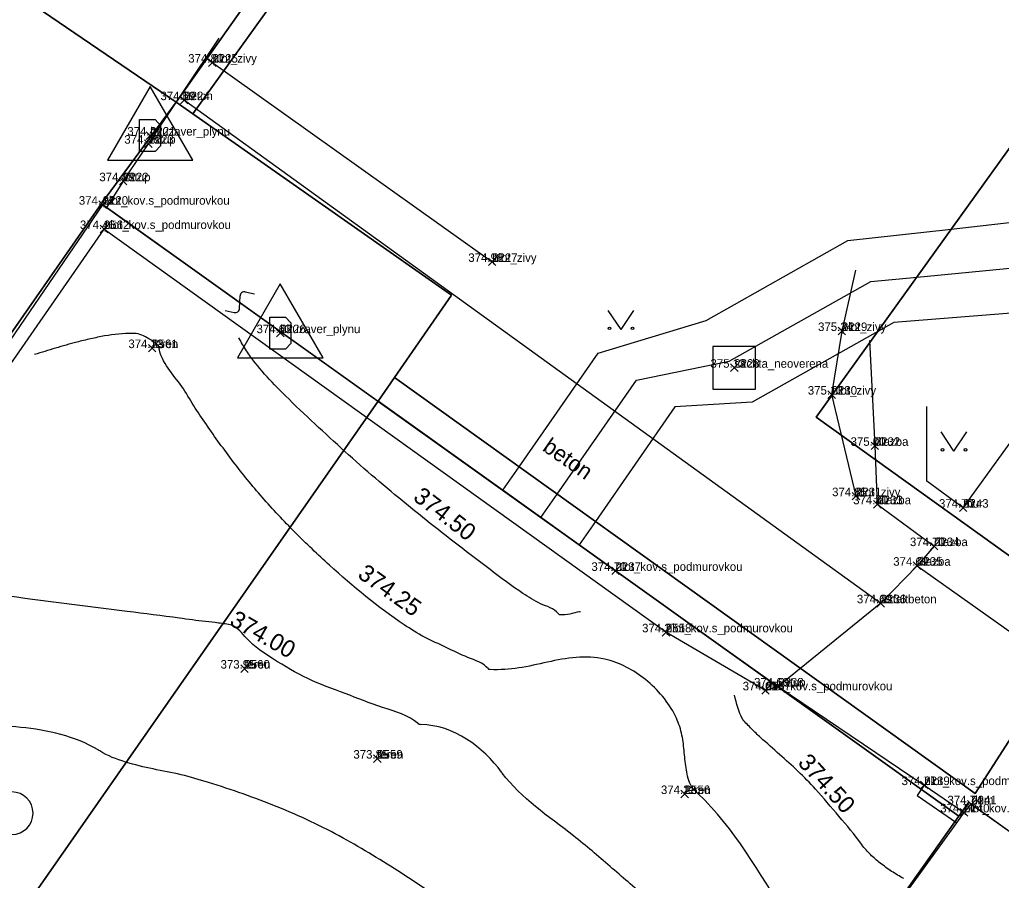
# Model space of a CAD drawing. Extents: x -400488 to -400124, y -1251493 to -1251223.
# Drawn here: x -400361.06 to -400338.08, y -1251307.23 to -1251287.06 of the extents above; entities that cross this region are included whole.
import ezdxf

# ---------------------------------------------------------------- set-up
doc = ezdxf.new("R2010")
doc.units = 0
for name, color, linetype in [('Level 20', 7, 'Continuous'), ('Level 21', 7, 'Continuous'), ('Level 22', 7, 'Continuous'), ('Level 23', 7, 'Continuous'), ('Level 31', 7, 'Continuous'), ('Level 32', 7, 'Continuous'), ('Level 34', 7, 'Continuous'), ('Level 35', 7, 'Continuous'), ('Level 36', 7, 'Continuous'), ('Level 49', 7, 'Continuous'), ('Level 50', 7, 'Continuous'), ('Level 60', 7, 'Continuous'), ('Level 63', 7, 'Continuous')]:
    doc.layers.add(name, color=color, linetype=linetype)

msp = doc.modelspace()

# ---------------------------------------------------------------- linework, layer by layer
at = {"layer": 'Level 20'}
for p, q in [((-400356.638, -1251288.158), (-400356.462, -1251287.982)), ((-400356.462, -1251288.158), (-400356.638, -1251287.982)), ((-400357.298, -1251289.038), (-400357.122, -1251288.862)), ((-400357.122, -1251289.038), (-400357.298, -1251288.862)), ((-400358.098, -1251289.868), (-400357.922, -1251289.692)), ((-400357.922, -1251289.868), (-400358.098, -1251289.692)), ((-400358.138, -1251290.058), (-400357.962, -1251289.882)), ((-400357.962, -1251290.058), (-400358.138, -1251289.882)), ((-400358.728, -1251290.938), (-400358.552, -1251290.762)), ((-400358.552, -1251290.938), (-400358.728, -1251290.762)), ((-400359.208, -1251291.488), (-400359.032, -1251291.312)), ((-400359.032, -1251291.488), (-400359.208, -1251291.312)), ((-400359.178, -1251292.058), (-400359.002, -1251291.882)), ((-400359.002, -1251292.058), (-400359.178, -1251291.882)), ((-400350.088, -1251292.828), (-400349.912, -1251292.652)), ((-400349.912, -1251292.828), (-400350.088, -1251292.652)), ((-400355.048, -1251294.498), (-400354.872, -1251294.322)), ((-400354.872, -1251294.498), (-400355.048, -1251294.322)), ((-400341.898, -1251294.448), (-400341.722, -1251294.272)), ((-400341.722, -1251294.448), (-400341.898, -1251294.272)), ((-400358.048, -1251294.848), (-400357.872, -1251294.672)), ((-400357.872, -1251294.848), (-400358.048, -1251294.672)), ((-400344.418, -1251295.308), (-400344.242, -1251295.132)), ((-400344.242, -1251295.308), (-400344.418, -1251295.132)), ((-400342.138, -1251295.938), (-400341.962, -1251295.762)), ((-400341.962, -1251295.938), (-400342.138, -1251295.762)), ((-400341.128, -1251297.138), (-400340.952, -1251296.962)), ((-400340.952, -1251297.138), (-400341.128, -1251296.962)), ((-400341.568, -1251298.318), (-400341.392, -1251298.142)), ((-400341.392, -1251298.318), (-400341.568, -1251298.142)), ((-400341.068, -1251298.508), (-400340.892, -1251298.332)), ((-400340.892, -1251298.508), (-400341.068, -1251298.332)), ((-400339.058, -1251298.588), (-400338.882, -1251298.412)), ((-400338.882, -1251298.588), (-400339.058, -1251298.412)), ((-400339.738, -1251299.488), (-400339.562, -1251299.312)), ((-400339.562, -1251299.488), (-400339.738, -1251299.312)), ((-400340.138, -1251299.948), (-400339.962, -1251299.772)), ((-400339.962, -1251299.948), (-400340.138, -1251299.772)), ((-400347.198, -1251300.068), (-400347.022, -1251299.892)), ((-400347.022, -1251300.068), (-400347.198, -1251299.892)), ((-400340.988, -1251300.828), (-400340.812, -1251300.652)), ((-400340.812, -1251300.828), (-400340.988, -1251300.652)), ((-400346.018, -1251301.508), (-400345.842, -1251301.332)), ((-400345.842, -1251301.508), (-400346.018, -1251301.332)), ((-400355.888, -1251302.358), (-400355.712, -1251302.182)), ((-400355.712, -1251302.358), (-400355.888, -1251302.182)), ((-400343.388, -1251302.778), (-400343.212, -1251302.602)), ((-400343.212, -1251302.778), (-400343.388, -1251302.602)), ((-400343.688, -1251302.868), (-400343.512, -1251302.692)), ((-400343.512, -1251302.868), (-400343.688, -1251302.692)), ((-400352.778, -1251304.468), (-400352.602, -1251304.292)), ((-400352.602, -1251304.468), (-400352.778, -1251304.292)), ((-400339.968, -1251305.088), (-400339.792, -1251304.912)), ((-400339.792, -1251305.088), (-400339.968, -1251304.912)), ((-400345.578, -1251305.298), (-400345.402, -1251305.122)), ((-400345.402, -1251305.298), (-400345.578, -1251305.122)), ((-400338.868, -1251305.538), (-400338.692, -1251305.362)), ((-400338.692, -1251305.538), (-400338.868, -1251305.362)), ((-400339.038, -1251305.728), (-400338.862, -1251305.552)), ((-400338.862, -1251305.728), (-400339.038, -1251305.552))]:
    msp.add_line(p, q, dxfattribs=at)
at = {"layer": 'Level 31'}
for points in [[(-400357.315, -1251288.874), (-400340.9, -1251300.74)], [(-400341.165, -1251294.579), (-400341.04, -1251297.05), (-400340.98, -1251298.42), (-400339.65, -1251299.4), (-400340.05, -1251299.86), (-400329.86, -1251307.09), (-400332.06, -1251310.22)], [(-400338.97, -1251298.5), (-400339.823, -1251297.879), (-400339.823, -1251296.129)]]:
    msp.add_lwpolyline(points, dxfattribs=at)
at = {"layer": 'Level 32'}
for points in [[(-400340.05, -1251299.86), (-400340.9, -1251300.74)], [(-400340.9, -1251300.74), (-400343.3, -1251302.69)]]:
    msp.add_lwpolyline(points, dxfattribs=at)
at = {"layer": 'Level 34'}
msp.add_lwpolyline([(-400343.58, -1251312.05), (-400339.12, -1251305.887), (-400338.95, -1251305.64), (-400338.78, -1251305.45), (-400332.06, -1251310.22), (-400331.92, -1251310.33)], dxfattribs=at)
at = {"layer": 'Level 35'}
for points in [[(-400358.05, -1251289.97), (-400356.392, -1251287.495)], [(-400356.703, -1251287.961), (-400350, -1251292.74)], [(-400358.64, -1251290.85), (-400358.05, -1251289.97)], [(-400358.64, -1251290.85), (-400359.034, -1251291.462)], [(-400380.18, -1251321.83), (-400371.19, -1251309.1), (-400359.12, -1251291.4)], [(-400359.12, -1251291.4), (-400347.11, -1251299.98), (-400343.3, -1251302.69)], [(-400343.3, -1251302.69), (-400343.6, -1251302.78), (-400345.93, -1251301.42), (-400359.09, -1251291.97), (-400380.09, -1251322.28), (-400384.96, -1251329.11), (-400372.26, -1251338.33), (-400358.88, -1251348.03)], [(-400341.495, -1251292.931), (-400341.81, -1251294.36), (-400342.05, -1251295.85), (-400341.48, -1251298.23)], [(-400338.97, -1251298.5), (-400337.4, -1251296.33), (-400320.87, -1251308.06), (-400319.57, -1251311.74)], [(-400343.3, -1251302.69), (-400339.88, -1251305)], [(-400339.88, -1251305), (-400340.05, -1251305.247), (-400339.12, -1251305.887)], [(-400339.88, -1251305), (-400338.95, -1251305.64)]]:
    msp.add_lwpolyline(points, dxfattribs=at)
at = {"layer": 'Level 36'}
for p, q in [((-400346.982, -1251294.328), (-400347.282, -1251293.878)), ((-400346.982, -1251294.328), (-400346.682, -1251293.878)), ((-400339.185, -1251297.174), (-400339.485, -1251296.724)), ((-400339.185, -1251297.174), (-400338.885, -1251296.724))]:
    msp.add_line(p, q, dxfattribs=at)
for centre in [(-400347.252, -1251294.298), (-400346.712, -1251294.298), (-400339.455, -1251297.144), (-400338.915, -1251297.144)]:
    msp.add_circle(centre, 0.03, dxfattribs=at)
msp.add_arc((-400361.25, -1251305.66), 0.5, 270, 90, dxfattribs=at)
at = {"layer": 'Level 49'}
for points in [[(-400341.424, -1251308.644), (-400342.03, -1251308.471), (-400342.935, -1251308.167), (-400343.035, -1251308.116), (-400343.078, -1251308.067), (-400343.099, -1251308.037), (-400345.18, -1251305.198), (-400345.34, -1251305.017), (-400345.356, -1251304.985), (-400345.46, -1251304.596), (-400345.506, -1251304.19), (-400345.565, -1251303.782), (-400345.707, -1251303.386), (-400346.407, -1251302.529), (-400346.859, -1251302.233), (-400347.364, -1251302.048), (-400348.033, -1251302.008), (-400348.705, -1251302.119), (-400349.377, -1251302.256), (-400350.045, -1251302.295), (-400350.075, -1251302.289), (-400350.088, -1251302.276), (-400350.569, -1251302.009), (-400351.077, -1251301.774), (-400351.583, -1251301.532), (-400352.06, -1251301.242), (-400353.809, -1251299.847), (-400354.617, -1251299.076), (-400355.383, -1251298.255), (-400356.062, -1251297.423), (-400356.69, -1251296.554), (-400356.986, -1251296.11), (-400357.268, -1251295.659), (-400357.802, -1251294.742), (-400357.815, -1251294.706), (-400357.816, -1251294.705), (-400358.039, -1251294.541), (-400358.38, -1251294.415), (-400358.42, -1251294.414), (-400359.074, -1251294.476), (-400359.403, -1251294.543), (-400359.728, -1251294.621), (-400360.224, -1251294.761), (-400360.717, -1251294.912)], [(-400347.928, -1251300.936), (-400347.952, -1251300.94), (-400348.414, -1251301.009), (-400348.427, -1251301.006), (-400348.449, -1251300.985), (-400348.865, -1251300.751), (-400349.076, -1251300.637), (-400349.279, -1251300.509), (-400350.045, -1251299.951), (-400350.799, -1251299.379), (-400351.542, -1251298.793), (-400352.276, -1251298.195), (-400353.004, -1251297.578), (-400353.712, -1251296.942), (-400355.093, -1251295.62), (-400355.552, -1251295.103), (-400355.753, -1251294.821), (-400355.932, -1251294.523)], [(-400342.338, -1251309.931), (-400342.926, -1251309.741), (-400343.403, -1251309.632), (-400343.7, -1251309.621), (-400343.998, -1251309.649), (-400345.067, -1251309.285), (-400345.407, -1251308.822), (-400345.721, -1251308.352), (-400346.087, -1251307.924), (-400346.398, -1251307.637), (-400347.239, -1251306.906), (-400348.093, -1251306.191), (-400349.765, -1251304.717), (-400349.777, -1251304.701), (-400351.677, -1251303.581), (-400351.722, -1251303.572), (-400351.728, -1251303.567), (-400352.566, -1251303.179), (-400353.445, -1251302.853), (-400354.315, -1251302.505), (-400355.121, -1251302.048), (-400355.747, -1251301.563), (-400356.101, -1251301.255), (-400356.253, -1251301.223), (-400356.406, -1251301.202), (-400356.712, -1251301.168), (-400357.324, -1251301.088), (-400358.547, -1251300.933), (-400364.448, -1251300.144)], [(-400340.363, -1251307.191), (-400340.645, -1251307.022), (-400340.78, -1251306.928), (-400340.913, -1251306.829), (-400341.14, -1251306.628), (-400341.339, -1251306.4), (-400341.349, -1251306.386), (-400341.878, -1251305.732), (-400342.429, -1251305.095), (-400342.838, -1251304.675), (-400343.273, -1251304.282), (-400343.712, -1251303.887), (-400343.926, -1251303.682), (-400344.029, -1251303.574), (-400344.131, -1251303.463), (-400344.136, -1251303.454), (-400344.324, -1251302.893)], [(-400343.209, -1251311.253), (-400343.532, -1251311.179), (-400344.172, -1251311.146), (-400344.816, -1251311.218), (-400345.461, -1251311.313), (-400346.105, -1251311.346), (-400346.116, -1251311.344), (-400346.287, -1251311.229), (-400346.431, -1251311.087), (-400346.569, -1251310.941), (-400346.723, -1251310.818), (-400346.9, -1251310.714), (-400347.083, -1251310.62), (-400347.265, -1251310.526), (-400347.439, -1251310.419), (-400348.288, -1251309.813), (-400349.125, -1251309.188), (-400349.962, -1251308.561), (-400350.811, -1251307.952), (-400352.125, -1251307.062), (-400352.799, -1251306.642), (-400353.489, -1251306.24), (-400355.033, -1251305.509), (-400356.643, -1251304.939), (-400357.283, -1251304.758), (-400357.939, -1251304.623), (-400358.583, -1251304.46), (-400359.188, -1251304.2), (-400359.21, -1251304.186), (-400359.228, -1251304.175), (-400361.036, -1251303.648), (-400361.979, -1251303.582), (-400362.918, -1251303.549), (-400362.946, -1251303.551), (-400363.275, -1251303.682), (-400363.596, -1251303.817), (-400364.226, -1251304.092), (-400365.474, -1251304.643), (-400368.248, -1251305.829)]]:
    msp.add_spline(points, degree=3, dxfattribs=at)
at = {"layer": 'Level 50'}
for points in [[(-400358.01, -1251288.626), (-400359.01, -1251290.357), (-400357.01, -1251290.357)], [(-400354.96, -1251293.255), (-400355.96, -1251294.988), (-400353.96, -1251294.988)]]:
    msp.add_lwpolyline(points, close=True, dxfattribs=at)
for points in [[(-400358.255, -1251289.405), (-400357.889, -1251289.405), (-400357.765, -1251289.541), (-400357.765, -1251290.019), (-400357.889, -1251290.155), (-400358.255, -1251290.155), (-400358.255, -1251289.405)], [(-400355.205, -1251294.035), (-400354.839, -1251294.035), (-400354.715, -1251294.171), (-400354.715, -1251294.649), (-400354.839, -1251294.785), (-400355.205, -1251294.785), (-400355.205, -1251294.035)]]:
    msp.add_lwpolyline(points, dxfattribs=at)
at = {"layer": 'Level 60'}
msp.add_lwpolyline([(-400344.83, -1251295.72), (-400343.83, -1251295.72), (-400343.83, -1251294.72), (-400344.83, -1251294.72)], close=True, dxfattribs=at)
at = {"layer": 'Level 63'}
for p, q in [((-400357.4, -1251289), (-400341.55, -1251266.53)), ((-400341.55, -1251266.53), (-400357.4, -1251289)), ((-400357.01, -1251289.27), (-400346.05, -1251274)), ((-400346.05, -1251274), (-400357.01, -1251289.27)), ((-400333.05, -1251283.33), (-400342.41, -1251296.38)), ((-400342.41, -1251296.38), (-400333.05, -1251283.33)), ((-400357.4, -1251289), (-400360.87, -1251286.63)), ((-400360.87, -1251286.63), (-400357.4, -1251289)), ((-400359.15, -1251291.37), (-400357.4, -1251289)), ((-400357.4, -1251289), (-400359.15, -1251291.37)), ((-400357.4, -1251289), (-400357.01, -1251289.27)), ((-400357.01, -1251289.27), (-400357.4, -1251289)), ((-400357.01, -1251289.27), (-400350.95, -1251293.52)), ((-400350.95, -1251293.52), (-400357.01, -1251289.27)), ((-400375.65, -1251315.05), (-400359.15, -1251291.37)), ((-400359.15, -1251291.37), (-400375.65, -1251315.05)), ((-400359.15, -1251291.37), (-400352.67, -1251296)), ((-400339.25, -1251291.97), (-400336.91, -1251291.7)), ((-400341.67, -1251292.24), (-400339.25, -1251291.97)), ((-400344.99, -1251294.11), (-400341.67, -1251292.24)), ((-400340.05, -1251293.1), (-400335.57, -1251292.66)), ((-400344.45, -1251295.07), (-400341.13, -1251293.2)), ((-400341.13, -1251293.2), (-400340.05, -1251293.1)), ((-400355.916, -1251293.832), (-400355.904, -1251293.538)), ((-400355.783, -1251293.444), (-400355.565, -1251293.492)), ((-400350.95, -1251293.52), (-400352.29, -1251295.45)), ((-400352.29, -1251295.45), (-400350.95, -1251293.52)), ((-400356.255, -1251293.878), (-400356.037, -1251293.926)), ((-400336.26, -1251293.82), (-400340.59, -1251294.16)), ((-400347.52, -1251294.88), (-400344.99, -1251294.11)), ((-400340.59, -1251294.16), (-400340.97, -1251294.37)), ((-400340.97, -1251294.37), (-400343.91, -1251296.03)), ((-400349.37, -1251297.54), (-400347.52, -1251294.88)), ((-400346.62, -1251295.51), (-400344.45, -1251295.07)), ((-400352.29, -1251295.45), (-400352.67, -1251296)), ((-400352.67, -1251296), (-400352.29, -1251295.45)), ((-400338.69, -1251305.2), (-400352.29, -1251295.45)), ((-400352.29, -1251295.45), (-400338.69, -1251305.2)), ((-400348.48, -1251298.18), (-400346.62, -1251295.51)), ((-400352.67, -1251296), (-400379.03, -1251333.83)), ((-400379.03, -1251333.83), (-400352.67, -1251296)), ((-400352.67, -1251296), (-400339.07, -1251305.73)), ((-400339.07, -1251305.73), (-400352.67, -1251296)), ((-400345.72, -1251296.14), (-400347.58, -1251298.82)), ((-400343.91, -1251296.03), (-400345.72, -1251296.14)), ((-400342.41, -1251296.38), (-400335.99, -1251300.99)), ((-400335.99, -1251300.99), (-400342.41, -1251296.38)), ((-400349.75, -1251298.09), (-400349.37, -1251297.54)), ((-400348.86, -1251298.73), (-400349.75, -1251298.09)), ((-400348.86, -1251298.73), (-400348.48, -1251298.18)), ((-400347.96, -1251299.37), (-400348.86, -1251298.73)), ((-400347.58, -1251298.82), (-400347.96, -1251299.37)), ((-400335.99, -1251300.99), (-400338.69, -1251305.2)), ((-400338.69, -1251305.2), (-400335.99, -1251300.99)), ((-400339.07, -1251305.73), (-400338.84, -1251305.4)), ((-400338.84, -1251305.4), (-400339.07, -1251305.73)), ((-400338.84, -1251305.4), (-400332.05, -1251310.27)), ((-400339.07, -1251305.73), (-400343.58, -1251312.08)), ((-400343.58, -1251312.08), (-400339.07, -1251305.73))]:
    msp.add_line(p, q, dxfattribs=at)
for centre, start, end in [((-400355.804, -1251293.542), 77.7527, 177.7631), ((-400356.016, -1251293.828), 257.753, 357.7631)]:
    msp.add_arc(centre, 0.1, start, end, dxfattribs=at)

# ---------------------------------------------------------------- texts
at = {"layer": 'Level 21'}
for s, p in [('2225', (-400356.55, -1251288.07)), ('2224', (-400357.21, -1251288.95)), ('2221', (-400358.01, -1251289.78)), ('2223', (-400358.05, -1251289.97)), ('2222', (-400358.64, -1251290.85)), ('2220', (-400359.12, -1251291.4)), ('2562', (-400359.09, -1251291.97)), ('2227', (-400350, -1251292.74)), ('2226', (-400354.96, -1251294.41)), ('2229', (-400341.81, -1251294.36)), ('2561', (-400357.96, -1251294.76)), ('2228', (-400344.33, -1251295.22)), ('2230', (-400342.05, -1251295.85)), ('2232', (-400341.04, -1251297.05)), ('2231', (-400341.48, -1251298.23)), ('2233', (-400340.98, -1251298.42)), ('2243', (-400338.97, -1251298.5)), ('2234', (-400339.65, -1251299.4)), ('2237', (-400347.11, -1251299.98)), ('2235', (-400340.05, -1251299.86)), ('2236', (-400340.9, -1251300.74)), ('2558', (-400345.93, -1251301.42)), ('2560', (-400355.8, -1251302.27)), ('2557', (-400343.6, -1251302.78)), ('2238', (-400343.3, -1251302.69)), ('2559', (-400352.69, -1251304.38)), ('2239', (-400339.88, -1251305)), ('2556', (-400345.49, -1251305.21)), ('2241', (-400338.78, -1251305.45)), ('2240', (-400338.95, -1251305.64))]:
    msp.add_text(s, height=0.2, dxfattribs=at).set_placement(p)
at = {"layer": 'Level 22'}
for s, p in [('plot_zivy', (-400356.55, -1251288.07)), ('beton', (-400357.21, -1251288.95)), ('hl.uzaver_plynu', (-400358.01, -1251289.78)), ('vstup', (-400358.05, -1251289.97)), ('vstup', (-400358.64, -1251290.85)), ('plot_kov.s_podmurovkou', (-400359.12, -1251291.4)), ('plot_kov.s_podmurovkou', (-400359.09, -1251291.97)), ('plot_zivy', (-400350, -1251292.74)), ('hl.uzaver_plynu', (-400354.96, -1251294.41)), ('plot_zivy', (-400341.81, -1251294.36)), ('teren', (-400357.96, -1251294.76)), ('sachta_neoverena', (-400344.33, -1251295.22)), ('plot_zivy', (-400342.05, -1251295.85)), ('dlazba', (-400341.04, -1251297.05)), ('plot_zivy', (-400341.48, -1251298.23)), ('dlazba', (-400340.98, -1251298.42)), ('mur', (-400338.97, -1251298.5)), ('dlazba', (-400339.65, -1251299.4)), ('plot_kov.s_podmurovkou', (-400347.11, -1251299.98)), ('dlazba', (-400340.05, -1251299.86)), ('asfaltbeton', (-400340.9, -1251300.74)), ('plot_kov.s_podmurovkou', (-400345.93, -1251301.42)), ('teren', (-400355.8, -1251302.27)), ('plot_kov.s_podmurovkou', (-400343.6, -1251302.78)), ('vstup', (-400343.3, -1251302.69)), ('teren', (-400352.69, -1251304.38)), ('plot_kov.s_podmurovkou', (-400339.88, -1251305)), ('teren', (-400345.49, -1251305.21)), ('dom', (-400338.78, -1251305.45)), ('plot_kov.s_podmurovkou', (-400338.95, -1251305.64))]:
    msp.add_text(s, height=0.2, dxfattribs=at).set_placement(p)
at = {"layer": 'Level 23'}
for s, p in [('374.80', (-400357.116, -1251288.07)), ('374.69', (-400357.768, -1251288.95)), ('374.41', (-400358.543, -1251289.78)), ('374.46', (-400358.613, -1251289.97)), ('374.48', (-400359.198, -1251290.85)), ('374.44', (-400359.678, -1251291.4)), ('374.46', (-400359.653, -1251291.97)), ('374.98', (-400350.558, -1251292.74)), ('374.63', (-400355.518, -1251294.41)), ('375.34', (-400342.368, -1251294.36)), ('374.23', (-400358.518, -1251294.76)), ('375.13', (-400344.888, -1251295.22)), ('375.13', (-400342.608, -1251295.85)), ('375.00', (-400341.606, -1251297.05)), ('374.85', (-400342.039, -1251298.23)), ('374.80', (-400341.546, -1251298.42)), ('374.70', (-400339.536, -1251298.5)), ('374.70', (-400340.216, -1251299.4)), ('374.70', (-400347.676, -1251299.98)), ('374.69', (-400340.608, -1251299.86)), ('374.69', (-400341.458, -1251300.74)), ('374.27', (-400346.488, -1251301.42)), ('373.95', (-400356.359, -1251302.27)), ('374.61', (-400344.133, -1251302.78)), ('374.60', (-400343.866, -1251302.69)), ('373.85', (-400353.249, -1251304.38)), ('374.71', (-400340.413, -1251305)), ('374.22', (-400346.048, -1251305.21)), ('374.74', (-400339.338, -1251305.45)), ('374.74', (-400339.508, -1251305.64))]:
    msp.add_text(s, height=0.2, dxfattribs=at).set_placement(p)
at = {"layer": 'Level 31'}
msp.add_text('beton', height=0.375, rotation=325.2178, dxfattribs=at).set_placement((-400348.845, -1251297.147))
at = {"layer": 'Level 49'}
for s, rotation, p in [('374.50', 322.311, (-400351.874, -1251298.302)), ('374.25', 324.4011, (-400353.174, -1251300.118)), ('374.00', 330.2017, (-400356.174, -1251301.233)), ('374.50', 312.3987, (-400342.862, -1251304.491))]:
    msp.add_text(s, height=0.4, rotation=rotation, dxfattribs=at).set_placement(p)

doc.saveas('drawing.dxf')
